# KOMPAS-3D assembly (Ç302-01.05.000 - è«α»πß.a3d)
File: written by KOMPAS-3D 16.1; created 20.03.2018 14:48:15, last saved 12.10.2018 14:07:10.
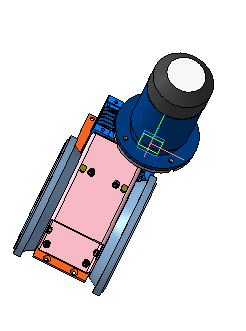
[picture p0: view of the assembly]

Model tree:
1. Массив по концентрической сетке:1  (2 pattern instances)
     Шаг 2 = 360
2. Массив по концентрической сетке:2  (4 pattern instances)
     Шаг 2 = 360
3. Массив по образцу:1  (4 pattern instances)
4. Массив по образцу:2
5. Экземпляр ( 1 )
6. Массив по образцу:3  (6 pattern instances)
7. Массив по образцу:4  (with: Экземпляр ( 1 ))
8. Сечение поверхностью:8
9. Сечение поверхностью:3
10. Сечение поверхностью:4  (labels: А302-01.05.000; C:\Program Files\ASCON\KOMPAS-3D V16\Sys\bo_atr.lat; SYSTEM_PROPERTY_ADDITIONAL_FOR:5.000000)
     Расстояние = 1; Расстояние = -5; Расстояние = -7; Расстояние = -0.8; Расстояние = -0.8

Referenced files in \\192.168.87.28\Konstructor_doc\Мембранные насосы\Мембранный электропривод\А302-00.00.000 - ASTRA-302 (МЭ200)\3Д ПВХ\Отработка\: А302-01.20.000 - Мотор-редуктор.a3d, Упор-1.m3d, А302-01.05.002 - Ловитель.m3d
Referenced files in C:\Program Files\ASCON\KOMPAS-3D V16\Libs\PartLib\DATA\vault\Methods\Kompas\3D\: PLib_Washer_1_712.m3d, PLib_Screw_DIN_7984_1500.m3d, PLib_Screw_ISO_10642_1500.m3d, PLib_Check_spring_rings_GOST_13942_911.m3d
Referenced files in C:\Program Files\ASCON\KOMPAS-3D V16\Libs\PartLib\DATA\VAULT\Methods\kompas\3d\: PLib_Washer_2_712.m3d, PLib_Bolt_1_900.m3d, PLib_Nut_OST92_900.m3d
Referenced files in \\192.168.87.28\Konstructor_doc\1 ПКИ 3D\1 Крепеж стандартный\Подшипник\: Подшипник 80х40х18 6208-2RS1 SKF.m3d
Referenced files in \\192.168.87.28\Konstructor_doc\Мембранные насосы\Мембранный электропривод\А302-00.00.000 - ASTRA-302 (МЭ200)\3Д ПВХ\: А302-01.05.011 - Ловитель.m3d, А302-01.05.015 - Фиксатор.m3d, А302-01.05.012 - Фиксатор.m3d, А302-01.05.001 - Основание.m3d, А302-01.05.002 - Ловитель.cdw, А302-01.05.001 - Основание.cdw, А302-01.05.012 - Фиксатор.cdw, А302-01.05.014 - Упор.cdw, А302-01.05.011 - Ловитель.cdw, А302-01.05.015 - Фиксатор.cdw
Referenced files in Z:\Мембранные насосы\Мембранный электропривод\А302-00.00.000 - ASTRA-302 (МЭ200)\3Д ПВХ\: А302-01.20.000 - Мотор-редуктор.cdw
Referenced files: GRAPHIC.TDP
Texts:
  @100~)2xA3
  Сталь 12Х18Н10Т ГОСТ 5632-72
  Шайба C.8.21 ГОСТ 11371-78
  Крепежное изделие ГОСТ
  Сталь 20 ГОСТ 1050-2013
  Шайба C 8.04.019 ГОСТ 6958-78
  Шайба C 8 ГОСТ 6958-78
  Сталь 30Х13 ГОСТ 5632-72
  Шайба 8 30Х13 019 ГОСТ 6402-70
  Шайба 8 ГОСТ 6402-70
  Болт М8-6gx30.58.019 ГОСТ 7805-70
  hole1
  hole2
  Болт М8-6gx30 ГОСТ 7805-70
  Гайка М8-6H.5.019 ГОСТ 5915-70
  bcut1
  hcut1
  cut1
  Гайка М8-6H ГОСТ 5915-70
  Подшипник 80х40х18 6208-2RS1 SKF
  Шайба C.5.21 ГОСТ 11371-78
  Шайба 5 30Х13 019 ГОСТ 6402-70
  Шайба 5 ГОСТ 6402-70
  Винт с цилиндрической головкой и шестигранным углублением под ключ ГОСТ Р ИСО 4762 - М5 x 16 - 6.8 - A9J
  Винт с цилиндрической головкой
  и шестигранным углублением под ключ
  ГОСТ Р ИСО  4762-М5 x 16
  Винт с цилиндрической головкой и шестигранным углублением под ключ
  Винт с цилиндрической головкой и шестигранным углублением под ключ ГОСТ Р ИСО  4762-М5 x 16-6.8-A9J
  Винт с цилиндрической головкой и шестигранным углублением под ключ ГОСТ Р ИСО 4762 - М5 x 12 - 6.8 - A9J
  ГОСТ Р ИСО  4762-М5 x 12
  Винт с цилиндрической головкой и шестигранным углублением под ключ ГОСТ Р ИСО  4762-М5 x 12-6.8-A9J
  Винт с потайной головкой и шестигранным углублением под ключ ГОСТ Р ИСО 10642 - М4 x 20 - 8.8 - A3J
  Винт с потайной головкой
  ГОСТ Р ИСО  10642-М4 x 20
  Винт с потайной головкой и шестигранным углублением под ключ
  Винт с потайной головкой и шестигранным углублением под ключ ГОСТ Р ИСО  10642-М4 x 20-8.8-A3J
  Винт с цилиндрической головкой и шестигранным углублением под ключ ГОСТ Р ИСО 4762 - М8 x 45 - 6.8 - A9J
  ГОСТ Р ИСО  4762-М8 x 45
  Винт с цилиндрической головкой и шестигранным углублением под ключ ГОСТ Р ИСО  4762-М8 x 45-6.8-A9J
  Винт с цилиндрической головкой и шестигранным углублением под ключ ГОСТ Р ИСО 4762 - М8 x 35 - 6.8 - A9J
  ГОСТ Р ИСО  4762-М8 x 35
  Винт с цилиндрической головкой и шестигранным углублением под ключ ГОСТ Р ИСО  4762-М8 x 35-6.8-A9J
  Сталь 65Г ГОСТ 14959-79
  Кольцо A40.65Г ГОСТ 13942-86
  Isp3
  ГОСТ 11371-78
  ГОСТ 6958-78
  ГОСТ 6402-70
  ГОСТ 7805-70
  М8-6gx30.58.019
  ГОСТ 5915-70
  ГОСТ Р ИСО 4762-2012
  ГОСТ Р ИСО 10642-2012
  ГОСТ 13942-86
